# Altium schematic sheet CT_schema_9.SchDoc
size 254 x 194 mm
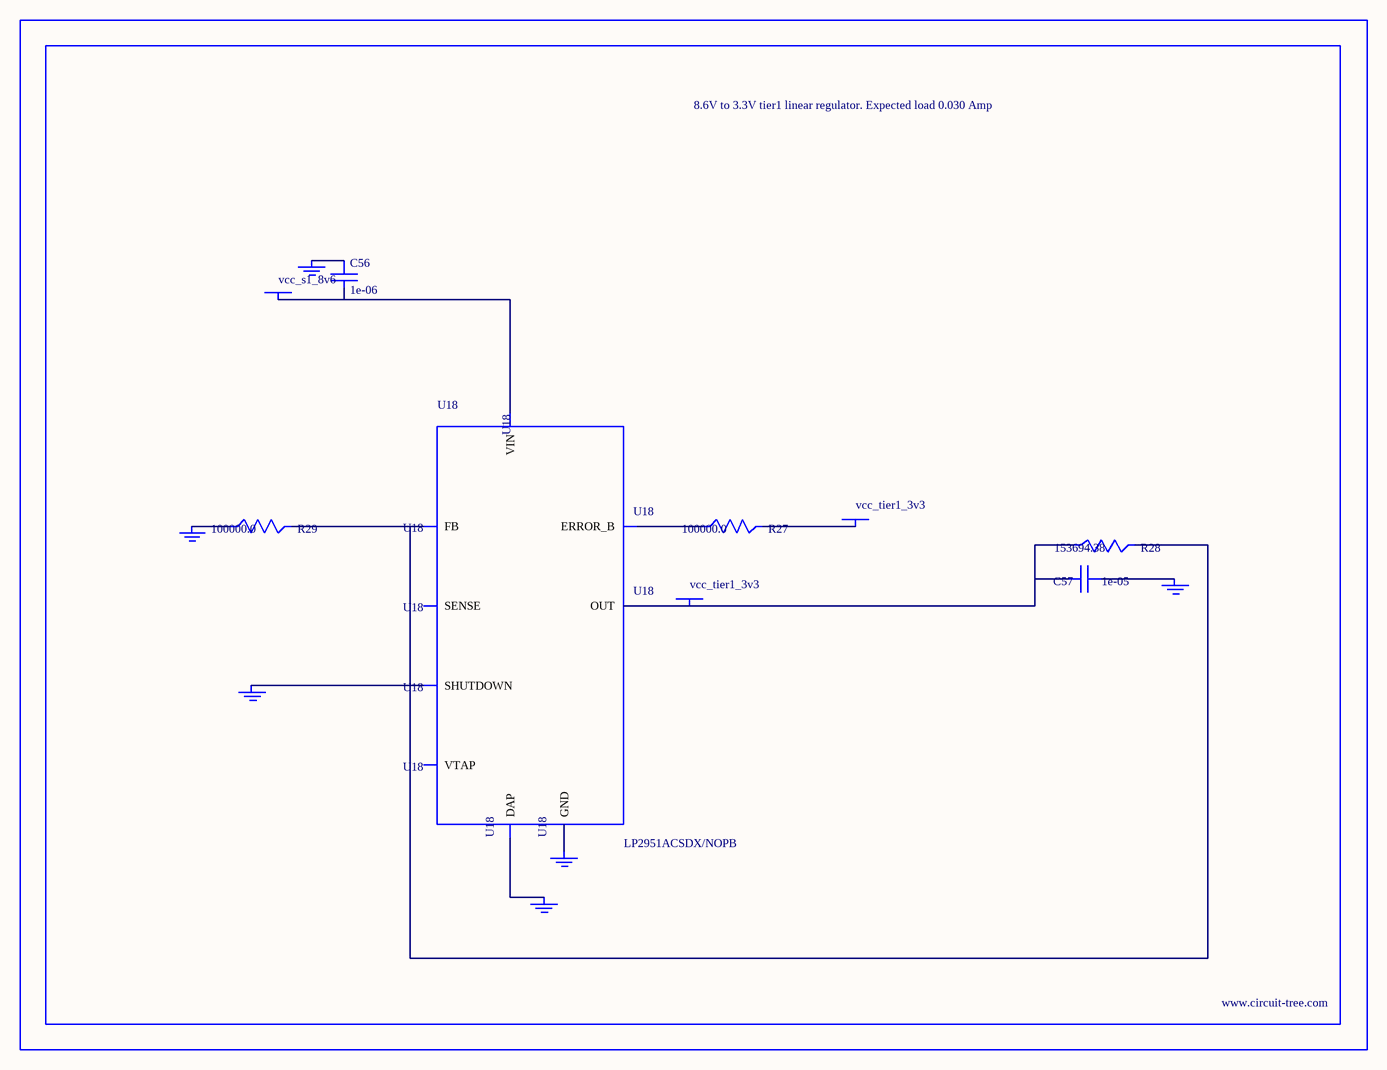
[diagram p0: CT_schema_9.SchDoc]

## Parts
BORDER8  (no value)
C56  1e-06  [C0603]
C57  1e-05  [C1210]
GND_INSTANCE_8_0  (no value)
GND_INSTANCE_8_1  (no value)
GND_INSTANCE_8_2  (no value)
GND_INSTANCE_8_3  (no value)
GND_INSTANCE_8_4  (no value)
GND_INSTANCE_8_5  (no value)
POWER_INSTANCE_8_0  vcc_tier1_3v3
POWER_INSTANCE_8_1  vcc_s1_8v6
POWER_INSTANCE_8_2  vcc_tier1_3v3
R27  100000.0  [R0603]
R28  153694.38  [R0603]
R29  100000.0  [R0603]
U18  LP2951ACSDX/NOPB  [WSON-8]

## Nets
NetC56_1: C56.1 GND_INSTANCE_8_3.0(GND)
NetC56_2: C56.2 POWER_INSTANCE_8_1.0(PWR) U18.8(VIN)
NetC57_1: C57.1 GND_INSTANCE_8_0.0(GND)
NetC57_2: C57.2 POWER_INSTANCE_8_2.0(PWR) R28.1 U18.1(OUT)
NetGND_INSTANCE_8_1_0: GND_INSTANCE_8_1.0(GND) U18.3(SHUTDOWN)
NetGND_INSTANCE_8_2_0: GND_INSTANCE_8_2.0(GND) R29.1
NetGND_INSTANCE_8_4_0: GND_INSTANCE_8_4.0(GND) U18.PAD(DAP)
NetGND_INSTANCE_8_5_0: GND_INSTANCE_8_5.0(GND) U18.4(GND)
NetPOWER_INSTANCE_8_0_0: POWER_INSTANCE_8_0.0(PWR) R27.2
NetR27_1: R27.1 U18.5(ERROR_B)
NetR28_2: R28.2 R29.2 U18.7(FB)

Not connected (* = marked no-connect by the designer): U18 2(SENSE) 6(VTAP)

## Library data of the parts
BORDER8 = BORDER_PAGE8
C56 = C0603C105K3RACTU
C57 = GRM32DR61E106MA12L
GND_INSTANCE_8_0-GND_INSTANCE_8_5 = GND
POWER_INSTANCE_8_0-POWER_INSTANCE_8_2 = PWR
R27 R29 = RC0603JR-07100KL
R28 = R28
